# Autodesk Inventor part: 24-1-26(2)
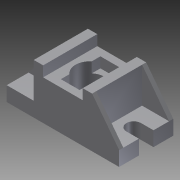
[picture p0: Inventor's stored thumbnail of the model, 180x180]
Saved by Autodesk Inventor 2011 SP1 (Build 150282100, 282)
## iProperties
Created: 2014-01
Part Number: 24-1-26(2)
Document SubType Name: Modeling
Designer: Administrator
Density: 1 g/cm^3
Author: Administrator
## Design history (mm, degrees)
sketch "草图1"
  geometry: L1 (-27, 13)-(27, 13); L2 (27, 13)-(27, -13); L3 (27, -13)-(-27, -13); L4 (-27, -13)-(-27, 13); 3 further points
  constraints: 8 end point, 2 midpoint, 2 parallel, 1 horizontal, 1 horizontal alignment, 1 perpendicular, 1 vertical alignment
  dimensions: "d0" = 54 distance of L1.start L1.end; "d1" = 26 distance of L3.end L1.start
extrude "拉伸1" new body sketch "草图1" distance "d2" = 7; taper "d3" = 0 deg
sketch "草图2"
  geometry: L1 (-27, 13)-(27, 13) reference; L2 (27, -13)-(-27, -13) reference; L3 (-14, 13)-(14, 13); L4 (14, 13)-(14, -13); L5 (14, -13)-(-14, -13); L6 (-14, -13)-(-14, 13); 2 further points
  constraints: 8 end point, 2 parallel, 2 point on line, 1 horizontal, 1 midpoint, 1 perpendicular, 1 vertical alignment
  dimensions: "d4" = 28 distance between parallel lines of L4 L6
extrude "拉伸2" join sketch "草图2" distance "d5" = 17; taper "d6" = 0 deg
sketch "草图3"
  geometry: L1 (-14, 13)-(14, 13) reference; L2 (14, -13)-(-14, -13) reference; L3 (-9.5, 13)-(9.5, 13); L4 (9.5, 13)-(9.5, -13); L5 (9.5, -13)-(-9.5, -13); L6 (-9.5, -13)-(-9.5, 13); 2 further points
  constraints: 8 end point, 2 parallel, 2 point on line, 1 horizontal, 1 midpoint, 1 perpendicular, 1 vertical alignment
  dimensions: "d7" = 19 distance between parallel lines of L4 L6
extrude "拉伸3" cut sketch "草图3" distance "d8" = 5; taper "d9" = 0 deg
sketch "草图4"
  geometry: L1 (-4.5, 9.5)-(4.5, 9.5); L2 (4.5, 9.5)-(4.5, -9.5); L3 (4.5, -9.5)-(-4.5, -9.5); L4 (-4.5, -9.5)-(-4.5, 9.5); 3 further points
  constraints: 8 end point, 2 midpoint, 2 parallel, 1 horizontal, 1 horizontal alignment, 1 perpendicular, 1 vertical alignment
  dimensions: "d10" = 9 distance of L1.start L1.end; "d11" = 19 distance of L1.end L2.end
extrude "拉伸4" cut sketch "草图4" distance "d12" = 5; taper "d13" = 0 deg
sketch "草图5"
  geometry: C1 r 7 at (0, 0); 1 further point
  constraints: 1 centre point, 1 coincident
  dimensions: "d14" = 14 diameter of C1
extrude "拉伸5" cut sketch "草图5" stored distance "d15" = 5; taper "d16" = 0 deg
sketch "草图6"
  geometry: L1 (27, 0)-(27, 7) reference; L2 (27, 7)-(14, 7) reference; L3 (14, 7)-(14, 24) reference; L4 (27, 7)-(14, 24); 1 further point
  constraints: 2 end point, 1 point on line
  dimensions: "d17" = 0 distance of L3.end L4.end
feature "加强筋1" sketch "草图6" dims "d18" = 1, "d19" = 5, "d20" = 0
sketch "草图7"
  geometry: L1 (41, 24)-(54, 7); 1 further point
  constraints: 2 end point
feature "加强筋2" sketch "草图7" dims "d21" = 1, "d22" = 2, "d23" = 0
mirror "镜像1"
sketch "草图8"
  geometry: L1 (27, 11)-(27, -11) reference; L2 (21, -3.5)-(27, -3.5); L3 (21, 3.5)-(27, 3.5); A1 r 3.5 centre (21, 0) between (21, 3.5) and (21, -3.5); 1 further point
  constraints: 4 end point, 2 perpendicular, 2 point on circle, 2 point on line, 2 tangent, 1 centre point
  dimensions: "d24" = 7 diameter of A1; "d25" = 6 distance from line of L1 A1.centre
extrude "拉伸6" cut sketch "草图8" stored distance "d26" = 5; taper "d27" = 0 deg
node "实体1"
